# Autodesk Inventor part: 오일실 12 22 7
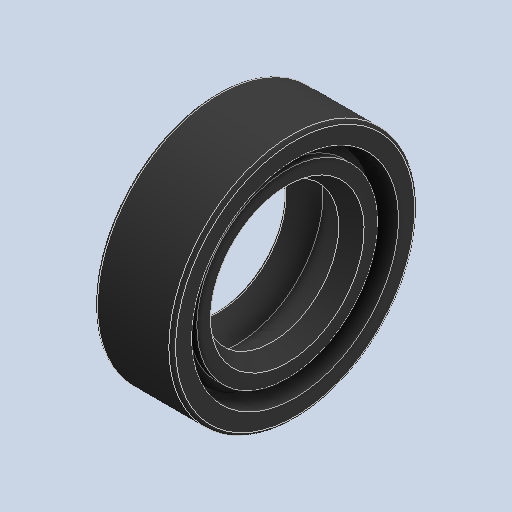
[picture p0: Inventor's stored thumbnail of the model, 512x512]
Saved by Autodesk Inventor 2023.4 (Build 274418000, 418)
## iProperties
Created: 2024-05
Part Number: 오일실 12 22 7
Material: 고무
Description: 오일-실
Document SubType Name: Modeling
Designer: edu-40
Density: 0.93 g/cm^3
Appearance: 기본값
Author: jhkim
Sending System: Autodesk Inventor 2025
Preprocessor: ST-DEVELOPER v20
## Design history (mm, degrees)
feature "Solid1"
node "솔리드1"
